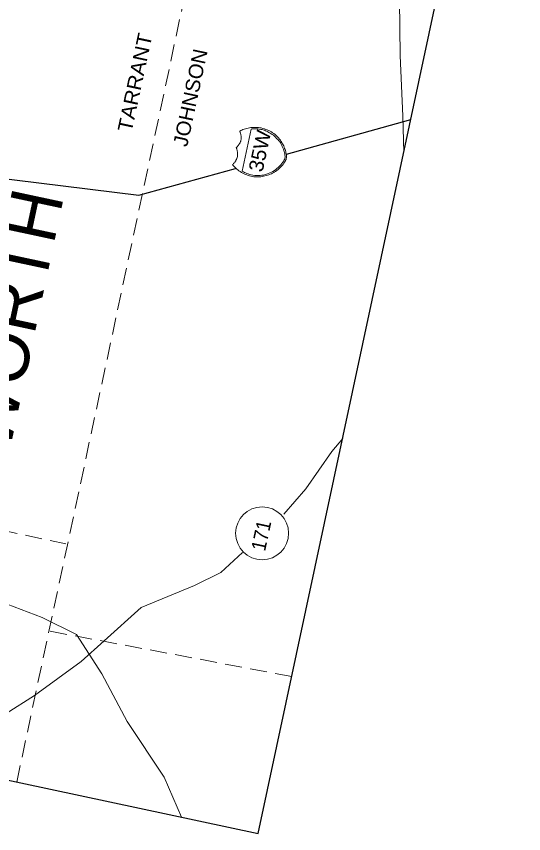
# Model space of a CAD drawing. Extents: x 2363411 to 2369126, y 6976878 to 6988319.
# Drawn here: x 2366047.6 to 2366227.2, y 6976877.7 to 6977167 of the extents above; entities that cross this region are included whole.
import ezdxf

# ---------------------------------------------------------------- set-up
doc = ezdxf.new("R2010")
doc.units = 0
doc.header["$LTSCALE"] = 2
doc.linetypes.add('MEDIUM_DASHED', pattern=[4.5, 3, -1.5])
doc.layers.add('62', color=7, linetype='Continuous', lineweight=13)
doc.layers.add('63', color=7, linetype='Continuous', lineweight=13)

msp = doc.modelspace()

# ---------------------------------------------------------------- linework, layer by layer
at = {"layer": '62', "linetype": 'MEDIUM_DASHED'}
for p, q in [((2366047.7, 6976895.971), (2366141.643, 6977335.641)), ((2365883.523, 6977019.043), (2366065.134, 6976980.263)), ((2366145.1, 6976933.33), (2366058.862, 6976949.503))]:
    msp.add_line(p, q, dxfattribs=at)
at = {"layer": '62', "lineweight": 25}
msp.add_line((2366143.17, 6977118.237), (2366187.224, 6977130.476), dxfattribs=at)
at = {"layer": '62'}
for p, q in [((2366150.089, 6976999.752), (2366142.264, 6976990.797)), ((2366120.015, 6976970.144), (2366127.655, 6976977.255)), ((2366110.586, 6976965.533), (2366120.015, 6976970.144))]:
    msp.add_line(p, q, dxfattribs=at)
at = {"layer": '62', "lineweight": 25}
for points in [[(2365678.211, 6976974.92), (2366133.213, 6976877.7), (2366227.156, 6977317.368), (2365772.152, 6977414.588)], [(2365917.348, 6977132.661), (2365965.303, 6977123.405), (2366019.993, 6977112.413), (2366090.955, 6977103.692), (2366125.134, 6977113.209)]]:
    msp.add_lwpolyline(points, dxfattribs=at)
at = {"layer": '62'}
for points in [[(2366096.932, 6977302.67), (2366104.486, 6977295.374), (2366118.795, 6977282.65), (2366135.856, 6977272.793), (2366149.213, 6977266.718), (2366158.553, 6977247.649), (2366168.364, 6977245.412), (2366174.148, 6977227.473), (2366180.022, 6977212.757), (2366183.73, 6977195.536), (2366183.185, 6977172.733), (2366183.468, 6977153.162), (2366184.402, 6977131.701), (2366184.733, 6977118.813)], [(2366126.001, 6977121.145), (2366126.129, 6977121.303), (2366126.26, 6977121.482), (2366126.357, 6977121.623), (2366126.487, 6977121.802), (2366126.575, 6977121.99), (2366126.677, 6977122.152), (2366126.758, 6977122.318), (2366126.823, 6977122.511), (2366126.904, 6977122.678), (2366126.991, 6977122.868), (2366127.029, 6977123.044), (2366127.071, 6977123.243), (2366127.11, 6977123.417), (2366127.146, 6977123.592), (2366127.148, 6977123.822), (2366127.139, 6977123.986), (2366127.153, 6977124.167), (2366127.153, 6977124.373), (2366127.128, 6977124.587), (2366127.122, 6977124.773), (2366127.077, 6977124.989), (2366127.049, 6977125.179), (2366126.999, 6977125.374), (2366126.949, 6977125.568), (2366126.898, 6977125.763), (2366126.829, 6977125.985), (2366126.738, 6977126.211), (2366126.645, 6977126.417), (2366127.008, 6977126.613), (2366127.391, 6977126.787), (2366127.794, 6977126.952), (2366128.242, 6977127.108), (2366128.664, 6977127.251), (2366129.128, 6977127.381), (2366129.612, 6977127.486), (2366130.117, 6977127.585), (2366130.637, 6977127.658), (2366131.155, 6977127.709), (2366131.689, 6977127.73), (2366132.196, 6977127.738), (2366132.721, 6977127.718), (2366133.246, 6977127.697), (2366133.758, 6977127.613), (2366134.274, 6977127.549), (2366134.814, 6977127.387), (2366135.361, 6977127.246), (2366135.892, 6977127.042), (2366136.384, 6977126.865), (2366136.894, 6977126.667), (2366137.384, 6977126.378), (2366137.859, 6977126.115), (2366138.303, 6977125.836), (2366138.742, 6977125.511), (2366139.173, 6977125.167), (2366139.558, 6977124.809), (2366139.963, 6977124.444), (2366140.333, 6977124.022), (2366140.678, 6977123.6), (2366141.024, 6977123.16), (2366141.333, 6977122.679), (2366141.58, 6977122.327), (2366141.8, 6977121.959), (2366142.011, 6977121.544), (2366142.205, 6977121.157), (2366142.366, 6977120.732), (2366142.529, 6977120.305), (2366142.674, 6977119.905), (2366142.819, 6977119.509), (2366142.941, 6977119.114), (2366143.022, 6977118.729), (2366143.1, 6977118.344), (2366143.158, 6977117.966), (2366143.179, 6977117.636), (2366143.178, 6977117.315), (2366143.156, 6977116.997), (2366143.123, 6977116.727)], [(2366143.123, 6977116.727), (2366143.062, 6977116.556), (2366143.03, 6977116.404), (2366142.971, 6977116.232), (2366142.894, 6977116.089), (2366142.811, 6977115.921), (2366142.731, 6977115.754), (2366142.617, 6977115.547), (2366142.509, 6977115.362), (2366142.384, 6977115.206), (2366142.274, 6977115.023), (2366142.118, 6977114.823), (2366141.988, 6977114.645), (2366141.851, 6977114.445), (2366141.706, 6977114.294), (2366141.525, 6977114.099), (2366141.368, 6977113.904), (2366141.194, 6977113.734), (2366141.014, 6977113.542), (2366140.82, 6977113.379), (2366140.646, 6977113.207), (2366140.469, 6977113.037), (2366140.252, 6977112.879), (2366140.077, 6977112.707), (2366139.885, 6977112.564), (2366139.667, 6977112.404), (2366139.476, 6977112.261), (2366139.285, 6977112.118), (2366139.075, 6977112.001), (2366138.857, 6977111.841), (2366138.672, 6977111.719), (2366138.465, 6977111.624), (2366138.256, 6977111.509), (2366137.848, 6977111.32), (2366137.367, 6977111.123), (2366136.922, 6977110.966), (2366136.473, 6977110.81), (2366136.005, 6977110.657), (2366135.54, 6977110.525), (2366135.08, 6977110.417), (2366134.605, 6977110.357), (2366134.127, 6977110.275), (2366133.633, 6977110.219), (2366133.129, 6977110.234), (2366132.644, 6977110.224), (2366132.136, 6977110.216), (2366131.663, 6977110.272), (2366131.126, 6977110.341), (2366130.615, 6977110.424), (2366130.117, 6977110.58), (2366129.62, 6977110.731), (2366129.129, 6977110.905), (2366128.641, 6977111.099), (2366128.18, 6977111.314), (2366127.703, 6977111.555), (2366127.253, 6977111.811), (2366126.801, 6977112.069), (2366126.385, 6977112.389), (2366125.987, 6977112.679), (2366125.618, 6977112.989), (2366125.289, 6977113.288), (2366124.948, 6977113.639), (2366124.642, 6977113.911), (2366124.368, 6977114.246), (2366124.115, 6977114.576), (2366124.284, 6977114.724), (2366124.459, 6977114.893), (2366124.613, 6977115.069), (2366124.739, 6977115.226), (2366124.869, 6977115.405), (2366124.993, 6977115.562), (2366125.102, 6977115.745), (2366125.227, 6977115.905), (2366125.308, 6977116.07), (2366125.412, 6977116.231), (2366125.498, 6977116.42), (2366125.559, 6977116.591), (2366125.649, 6977116.805), (2366125.727, 6977116.947), (2366125.765, 6977117.123), (2366125.811, 6977117.343), (2366125.848, 6977117.519), (2366125.886, 6977117.695), (2366125.885, 6977117.901), (2366125.879, 6977118.087), (2366125.893, 6977118.268), (2366125.886, 6977118.453), (2366125.867, 6977118.688), (2366125.863, 6977118.875), (2366125.812, 6977119.07), (2366125.783, 6977119.261), (2366125.737, 6977119.477), (2366125.691, 6977119.693), (2366125.641, 6977119.888), (2366125.57, 6977120.087), (2366125.476, 6977120.294), (2366125.386, 6977120.517), (2366125.553, 6977120.666), (2366125.724, 6977120.813), (2366125.876, 6977120.989), (2366126.001, 6977121.145)], [(2366150.089, 6976999.752), (2366159.26, 6977012.957), (2366163.099, 6977017.567)], [(2365990.291, 6976908.24), (2365995.575, 6976910.999), (2366012.158, 6976918.295), (2366029.791, 6976919.405), (2366044.007, 6976920.255), (2366053.944, 6976926.599), (2366070.505, 6976938.615), (2366078.644, 6976946.012), (2366091.784, 6976957.768), (2366110.586, 6976965.533)], [(2366044.33, 6976958.911), (2366056.7, 6976954.245), (2366068.834, 6976948.245), (2366077.828, 6976934.335), (2366086.801, 6976917.439), (2366099.873, 6976897.735), (2366106.059, 6976883.502)]]:
    msp.add_lwpolyline(points, dxfattribs=at)
msp.add_lwpolyline([(2366130.736, 6977127.154), (2366127.554, 6977112.254), (2366127.755, 6977112.121), (2366128.021, 6977111.97), (2366128.309, 6977111.817), (2366128.689, 6977111.643), (2366129.106, 6977111.44), (2366129.592, 6977111.244), (2366130.11, 6977111.086), (2366130.729, 6977110.952), (2366131.322, 6977110.829), (2366131.972, 6977110.735), (2366132.583, 6977110.697), (2366133.206, 6977110.701), (2366133.834, 6977110.728), (2366134.421, 6977110.787), (2366135.035, 6977110.862), (2366135.62, 6977111.013), (2366136.182, 6977111.169), (2366136.75, 6977111.349), (2366137.331, 6977111.592), (2366137.889, 6977111.839), (2366138.418, 6977112.164), (2366138.955, 6977112.509), (2366139.445, 6977112.865), (2366139.943, 6977113.266), (2366140.189, 6977113.442), (2366140.4, 6977113.673), (2366140.649, 6977113.873), (2366140.865, 6977114.126), (2366141.072, 6977114.337), (2366141.302, 6977114.562), (2366141.468, 6977114.803), (2366141.679, 6977115.034), (2366141.846, 6977115.274), (2366141.984, 6977115.498), (2366142.153, 6977115.741), (2366142.287, 6977115.941), (2366142.41, 6977116.189), (2366142.5, 6977116.4), (2366142.569, 6977116.617), (2366142.638, 6977116.833), (2366142.682, 6977117.147), (2366142.697, 6977117.532), (2366142.64, 6977117.913), (2366142.591, 6977118.338), (2366142.518, 6977118.742), (2366142.403, 6977119.182), (2366142.264, 6977119.604), (2366142.108, 6977120.051), (2366141.927, 6977120.505), (2366141.721, 6977120.939), (2366141.534, 6977121.348), (2366141.34, 6977121.735), (2366141.147, 6977122.122), (2366140.921, 6977122.468), (2366140.69, 6977122.794), (2366140.486, 6977123.021), (2366140.099, 6977123.472), (2366139.72, 6977123.852), (2366139.343, 6977124.231), (2366138.938, 6977124.594), (2366138.569, 6977124.926), (2366138.172, 6977125.222), (2366137.792, 6977125.485), (2366137.385, 6977125.733), (2366136.999, 6977125.975), (2366136.611, 6977126.197), (2366136.21, 6977126.377), (2366135.786, 6977126.535), (2366135.38, 6977126.689), (2366134.972, 6977126.824), (2366134.556, 6977126.935), (2366134.162, 6977127.019), (2366133.543, 6977127.151), (2366133.008, 6977127.221), (2366132.48, 6977127.241), (2366132.028, 6977127.269), (2366131.608, 6977127.244), (2366131.275, 6977127.198), (2366130.97, 6977127.171)], close=True, dxfattribs=at)
msp.add_circle((2366134.565, 6976984.021), 9.364, dxfattribs=at)
at = {"layer": '63', "linetype": 'MEDIUM_DASHED'}
for p, q in [((2366047.7, 6976895.971), (2366141.643, 6977335.641)), ((2365883.523, 6977019.043), (2366065.134, 6976980.263)), ((2366145.1, 6976933.33), (2366058.862, 6976949.503))]:
    msp.add_line(p, q, dxfattribs=at)
at = {"layer": '63', "lineweight": 25}
msp.add_line((2366143.17, 6977118.237), (2366187.224, 6977130.476), dxfattribs=at)
at = {"layer": '63'}
for p, q in [((2366150.089, 6976999.752), (2366142.264, 6976990.797)), ((2366120.015, 6976970.144), (2366127.655, 6976977.255)), ((2366110.586, 6976965.533), (2366120.015, 6976970.144))]:
    msp.add_line(p, q, dxfattribs=at)
at = {"layer": '63', "lineweight": 25}
for points in [[(2365678.211, 6976974.92), (2366133.213, 6976877.7), (2366227.156, 6977317.368), (2365772.152, 6977414.588)], [(2365917.348, 6977132.661), (2365965.303, 6977123.405), (2366019.993, 6977112.413), (2366090.955, 6977103.692), (2366125.134, 6977113.209)]]:
    msp.add_lwpolyline(points, dxfattribs=at)
at = {"layer": '63'}
for points in [[(2366096.932, 6977302.67), (2366104.486, 6977295.374), (2366118.795, 6977282.65), (2366135.856, 6977272.793), (2366149.213, 6977266.718), (2366158.553, 6977247.649), (2366168.364, 6977245.412), (2366174.148, 6977227.473), (2366180.022, 6977212.757), (2366183.73, 6977195.536), (2366183.185, 6977172.733), (2366183.468, 6977153.162), (2366184.402, 6977131.701), (2366184.733, 6977118.813)], [(2366126.001, 6977121.145), (2366126.129, 6977121.303), (2366126.26, 6977121.482), (2366126.357, 6977121.623), (2366126.487, 6977121.802), (2366126.575, 6977121.99), (2366126.677, 6977122.152), (2366126.758, 6977122.318), (2366126.823, 6977122.511), (2366126.904, 6977122.678), (2366126.991, 6977122.868), (2366127.029, 6977123.044), (2366127.071, 6977123.243), (2366127.11, 6977123.417), (2366127.146, 6977123.592), (2366127.148, 6977123.822), (2366127.139, 6977123.986), (2366127.153, 6977124.167), (2366127.153, 6977124.373), (2366127.128, 6977124.587), (2366127.122, 6977124.773), (2366127.077, 6977124.989), (2366127.049, 6977125.179), (2366126.999, 6977125.374), (2366126.949, 6977125.568), (2366126.898, 6977125.763), (2366126.829, 6977125.985), (2366126.738, 6977126.211), (2366126.645, 6977126.417), (2366127.008, 6977126.613), (2366127.391, 6977126.787), (2366127.794, 6977126.952), (2366128.242, 6977127.108), (2366128.664, 6977127.251), (2366129.128, 6977127.381), (2366129.612, 6977127.486), (2366130.117, 6977127.585), (2366130.637, 6977127.658), (2366131.155, 6977127.709), (2366131.689, 6977127.73), (2366132.196, 6977127.738), (2366132.721, 6977127.718), (2366133.246, 6977127.697), (2366133.758, 6977127.613), (2366134.274, 6977127.549), (2366134.814, 6977127.387), (2366135.361, 6977127.246), (2366135.892, 6977127.042), (2366136.384, 6977126.865), (2366136.894, 6977126.667), (2366137.384, 6977126.378), (2366137.859, 6977126.115), (2366138.303, 6977125.836), (2366138.742, 6977125.511), (2366139.173, 6977125.167), (2366139.558, 6977124.809), (2366139.963, 6977124.444), (2366140.333, 6977124.022), (2366140.678, 6977123.6), (2366141.024, 6977123.16), (2366141.333, 6977122.679), (2366141.58, 6977122.327), (2366141.8, 6977121.959), (2366142.011, 6977121.544), (2366142.205, 6977121.157), (2366142.366, 6977120.732), (2366142.529, 6977120.305), (2366142.674, 6977119.905), (2366142.819, 6977119.509), (2366142.941, 6977119.114), (2366143.022, 6977118.729), (2366143.1, 6977118.344), (2366143.158, 6977117.966), (2366143.179, 6977117.636), (2366143.178, 6977117.315), (2366143.156, 6977116.997), (2366143.123, 6977116.727)], [(2366143.123, 6977116.727), (2366143.062, 6977116.556), (2366143.03, 6977116.404), (2366142.971, 6977116.232), (2366142.894, 6977116.089), (2366142.811, 6977115.921), (2366142.731, 6977115.754), (2366142.617, 6977115.547), (2366142.509, 6977115.362), (2366142.384, 6977115.206), (2366142.274, 6977115.023), (2366142.118, 6977114.823), (2366141.988, 6977114.645), (2366141.851, 6977114.445), (2366141.706, 6977114.294), (2366141.525, 6977114.099), (2366141.368, 6977113.904), (2366141.194, 6977113.734), (2366141.014, 6977113.542), (2366140.82, 6977113.379), (2366140.646, 6977113.207), (2366140.469, 6977113.037), (2366140.252, 6977112.879), (2366140.077, 6977112.707), (2366139.885, 6977112.564), (2366139.667, 6977112.404), (2366139.476, 6977112.261), (2366139.285, 6977112.118), (2366139.075, 6977112.001), (2366138.857, 6977111.841), (2366138.672, 6977111.719), (2366138.465, 6977111.624), (2366138.256, 6977111.509), (2366137.848, 6977111.32), (2366137.367, 6977111.123), (2366136.922, 6977110.966), (2366136.473, 6977110.81), (2366136.005, 6977110.657), (2366135.54, 6977110.525), (2366135.08, 6977110.417), (2366134.605, 6977110.357), (2366134.127, 6977110.275), (2366133.633, 6977110.219), (2366133.129, 6977110.234), (2366132.644, 6977110.224), (2366132.136, 6977110.216), (2366131.663, 6977110.272), (2366131.126, 6977110.341), (2366130.615, 6977110.424), (2366130.117, 6977110.58), (2366129.62, 6977110.731), (2366129.129, 6977110.905), (2366128.641, 6977111.099), (2366128.18, 6977111.314), (2366127.703, 6977111.555), (2366127.253, 6977111.811), (2366126.801, 6977112.069), (2366126.385, 6977112.389), (2366125.987, 6977112.679), (2366125.618, 6977112.989), (2366125.289, 6977113.288), (2366124.948, 6977113.639), (2366124.642, 6977113.911), (2366124.368, 6977114.246), (2366124.115, 6977114.576), (2366124.284, 6977114.724), (2366124.459, 6977114.893), (2366124.613, 6977115.069), (2366124.739, 6977115.226), (2366124.869, 6977115.405), (2366124.993, 6977115.562), (2366125.102, 6977115.745), (2366125.227, 6977115.905), (2366125.308, 6977116.07), (2366125.412, 6977116.231), (2366125.498, 6977116.42), (2366125.559, 6977116.591), (2366125.649, 6977116.805), (2366125.727, 6977116.947), (2366125.765, 6977117.123), (2366125.811, 6977117.343), (2366125.848, 6977117.519), (2366125.886, 6977117.695), (2366125.885, 6977117.901), (2366125.879, 6977118.087), (2366125.893, 6977118.268), (2366125.886, 6977118.453), (2366125.867, 6977118.688), (2366125.863, 6977118.875), (2366125.812, 6977119.07), (2366125.783, 6977119.261), (2366125.737, 6977119.477), (2366125.691, 6977119.693), (2366125.641, 6977119.888), (2366125.57, 6977120.087), (2366125.476, 6977120.294), (2366125.386, 6977120.517), (2366125.553, 6977120.666), (2366125.724, 6977120.813), (2366125.876, 6977120.989), (2366126.001, 6977121.145)], [(2366150.089, 6976999.752), (2366159.26, 6977012.957), (2366163.099, 6977017.567)], [(2365990.291, 6976908.24), (2365995.575, 6976910.999), (2366012.158, 6976918.295), (2366029.791, 6976919.405), (2366044.007, 6976920.255), (2366053.944, 6976926.599), (2366070.505, 6976938.615), (2366078.644, 6976946.012), (2366091.784, 6976957.768), (2366110.586, 6976965.533)], [(2366044.33, 6976958.911), (2366056.7, 6976954.245), (2366068.834, 6976948.245), (2366077.828, 6976934.335), (2366086.801, 6976917.439), (2366099.873, 6976897.735), (2366106.059, 6976883.502)]]:
    msp.add_lwpolyline(points, dxfattribs=at)
msp.add_lwpolyline([(2366130.736, 6977127.154), (2366127.554, 6977112.254), (2366127.755, 6977112.121), (2366128.021, 6977111.97), (2366128.309, 6977111.817), (2366128.689, 6977111.643), (2366129.106, 6977111.44), (2366129.592, 6977111.244), (2366130.11, 6977111.086), (2366130.729, 6977110.952), (2366131.322, 6977110.829), (2366131.972, 6977110.735), (2366132.583, 6977110.697), (2366133.206, 6977110.701), (2366133.834, 6977110.728), (2366134.421, 6977110.787), (2366135.035, 6977110.862), (2366135.62, 6977111.013), (2366136.182, 6977111.169), (2366136.75, 6977111.349), (2366137.331, 6977111.592), (2366137.889, 6977111.839), (2366138.418, 6977112.164), (2366138.955, 6977112.509), (2366139.445, 6977112.865), (2366139.943, 6977113.266), (2366140.189, 6977113.442), (2366140.4, 6977113.673), (2366140.649, 6977113.873), (2366140.865, 6977114.126), (2366141.072, 6977114.337), (2366141.302, 6977114.562), (2366141.468, 6977114.803), (2366141.679, 6977115.034), (2366141.846, 6977115.274), (2366141.984, 6977115.498), (2366142.153, 6977115.741), (2366142.287, 6977115.941), (2366142.41, 6977116.189), (2366142.5, 6977116.4), (2366142.569, 6977116.617), (2366142.638, 6977116.833), (2366142.682, 6977117.147), (2366142.697, 6977117.532), (2366142.64, 6977117.913), (2366142.591, 6977118.338), (2366142.518, 6977118.742), (2366142.403, 6977119.182), (2366142.264, 6977119.604), (2366142.108, 6977120.051), (2366141.927, 6977120.505), (2366141.721, 6977120.939), (2366141.534, 6977121.348), (2366141.34, 6977121.735), (2366141.147, 6977122.122), (2366140.921, 6977122.468), (2366140.69, 6977122.794), (2366140.486, 6977123.021), (2366140.099, 6977123.472), (2366139.72, 6977123.852), (2366139.343, 6977124.231), (2366138.938, 6977124.594), (2366138.569, 6977124.926), (2366138.172, 6977125.222), (2366137.792, 6977125.485), (2366137.385, 6977125.733), (2366136.999, 6977125.975), (2366136.611, 6977126.197), (2366136.21, 6977126.377), (2366135.786, 6977126.535), (2366135.38, 6977126.689), (2366134.972, 6977126.824), (2366134.556, 6977126.935), (2366134.162, 6977127.019), (2366133.543, 6977127.151), (2366133.008, 6977127.221), (2366132.48, 6977127.241), (2366132.028, 6977127.269), (2366131.608, 6977127.244), (2366131.275, 6977127.198), (2366130.97, 6977127.171)], close=True, dxfattribs=at)
msp.add_circle((2366134.565, 6976984.021), 9.364, dxfattribs=at)

# ---------------------------------------------------------------- texts
at = {"layer": '62'}
for s, width, p in [('TARRANT', 1.1, (2366088.359, 6977125.78)), ('JOHNSON', 1.05, (2366108.012, 6977120.616)), ('35W', 1.05, (2366134.699, 6977111.648)), ('171', 0.95, (2366135.61, 6976977.443))]:
    msp.add_text(s, height=5.099, rotation=77.939, dxfattribs=dict(at, width=width)).set_placement(p)
msp.add_text('WORTH', height=18.39, rotation=77.939, dxfattribs=at).set_placement((2366045.054, 6977012.484))
at = {"layer": '63'}
for s, width, p in [('TARRANT', 1.1, (2366088.359, 6977125.78)), ('JOHNSON', 1.05, (2366108.012, 6977120.616)), ('35W', 1.05, (2366134.699, 6977111.648)), ('171', 0.95, (2366135.61, 6976977.443))]:
    msp.add_text(s, height=5.099, rotation=77.939, dxfattribs=dict(at, width=width)).set_placement(p)
msp.add_text('WORTH', height=18.39, rotation=77.939, dxfattribs=at).set_placement((2366045.054, 6977012.484))

doc.saveas('drawing.dxf')
